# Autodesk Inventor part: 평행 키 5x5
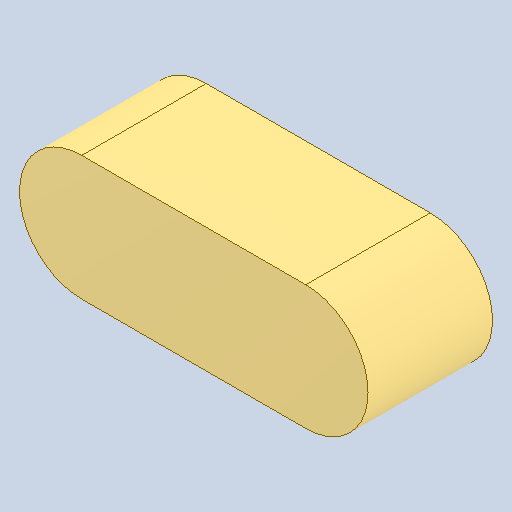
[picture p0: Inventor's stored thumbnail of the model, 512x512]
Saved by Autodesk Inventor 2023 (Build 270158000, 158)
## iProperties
Created: 2025-04
Part Number: 평행 키 5x5
Material: 강철, 연강
Document SubType Name: Modeling
Designer: user
Density: 7.86 g/cm^3
Appearance: 기본값
Author: jhkim
Revision Number: 1
Sending System: Autodesk Inventor 2026
Preprocessor: ST-DEVELOPER v20.1
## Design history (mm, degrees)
feature "솔리드1"
node "솔리드2"
